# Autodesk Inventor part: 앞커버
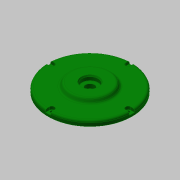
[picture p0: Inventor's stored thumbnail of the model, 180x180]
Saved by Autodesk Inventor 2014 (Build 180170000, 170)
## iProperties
Created: 2016-11
Part Number: 앞커버
Material: 일반
Document SubType Name: Modeling
Designer: mduedu
Density: 1 g/cm^3
Mass: 145.694 g
Surface Area: 366.671 cm^2
Volume: 145.694 cm^3
Appearance: 진녹색
Author: mduedu
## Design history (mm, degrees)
sketch "스케치1"
  geometry: L1 (22, -12.5)-(22, -30); L2 (22, -30)-(16, -33.464); L3 (16, -33.464)-(16, -65); L4 (16, -65)-(8, -65); L5 (8, -65)-(8, -53); L6 (8, -53)-(0, -53); L7 (0, -53)-(0, -14); L8 (0, 0)-(22, 0); L9 (8, -14)-(8, -7); L10 (8, -7)-(14.5, -7); L11 (14.5, -7)-(14.5, -12.5); L12 (0, -14)-(8, -14); L13 (14.5, -12.5)-(22, -12.5)
  constraints: 26 end point, 8 parallel, 3 perpendicular, 2 horizontal, 2 vertical alignment, 1 collinear
  dimensions: "d0" = 8 distance of L5.end L6.end; "d2" = 8 distance of L3.end L4.end; "d3" = 6 distance between parallel lines of L1 L3; "d4" = 120 deg angle of L3 L2; "d5" = 7.5 distance of L11.end L1.start; "d6" = 60 diameter of L1.end L8; "d7" = 14 diameter of L10 L8; "d8" = 28 diameter of L12 L8; "d9" = 25 diameter of L13 L8; "d10" = 106 diameter of L6 L8; "d11" = 130 diameter of L4 L8
revolve "회전1" sketch "스케치1" stored, may be unused: angle "d12" = 90 deg
fillet "모깎기1" dims "d13" = 0.3
fillet "모깎기2" dims "d14" = 3
chamfer "모따기1" distance "d15" = 1; stored, may be unused: second distance "d16" = 2, angle "d17" = 45 deg
fillet "모깎기3" dims "d18" = 0.3
chamfer "모따기2" distance "d36" = 2; stored, may be unused: second distance "d37" = 2, angle "d38" = 30 deg
sketch "스케치3"
  geometry: C1 r 65 at (0, 0) reference; A1 r 59 centre (0, 0) between (0, 59) and (59, 0); 2 further points
  constraints: 4 point on circle, 2 horizontal alignment, 2 vertical alignment, 1 centre point, 1 coincident
  dimensions: "d33" = 118 diameter of A1
sketch "스케치4"
  geometry: 4 further points
  constraints: 4 other
hole "구멍2" sketch "스케치4" at (0, 59), (-59, 0), (59, 0), (0, -59) diameter "d39" = 4.5; stored, may be unused: countersink angle "d43" = 90 deg, drill point angle "d45" = 0 deg; dims "d40" = 6, "d41" = 8, "d42" = 4.6, "d44" = 8
sketch "스케치6"
  geometry: L1 (-4, 5.877)-(-4, 0); L2 (4, 5.877)-(4, 0); A1 r 4 centre (0, 0) between (-2.712, 2.941) and (2.712, 2.941) reference; A2 r 65 centre (0, -59) between (-4, 5.877) and (4, 5.877) reference; 1 further point
  constraints: 4 end point, 4 point on circle, 2 tangent, 2 vertical
extrude "돌출2" cut sketch "스케치6" stored distance "d51" = 10; taper "d52" = 0 deg
sketch "스케치5"
  geometry: C1 r 22 at (0, 0); C2 r 45 at (0, 0); 1 further point
  constraints: 2 centre point, 2 coincident
  dimensions: "d46" = 44 diameter of C1; "d47" = 90 diameter of C2
extrude "돌출1" cut sketch "스케치5" distance "d48" = 8; taper "d49" = 0 deg
fillet "모깎기4" dims "d50" = 3
node "솔리드1"
pattern_circular "원형 패턴1" dims angle "d54" = 360 deg
